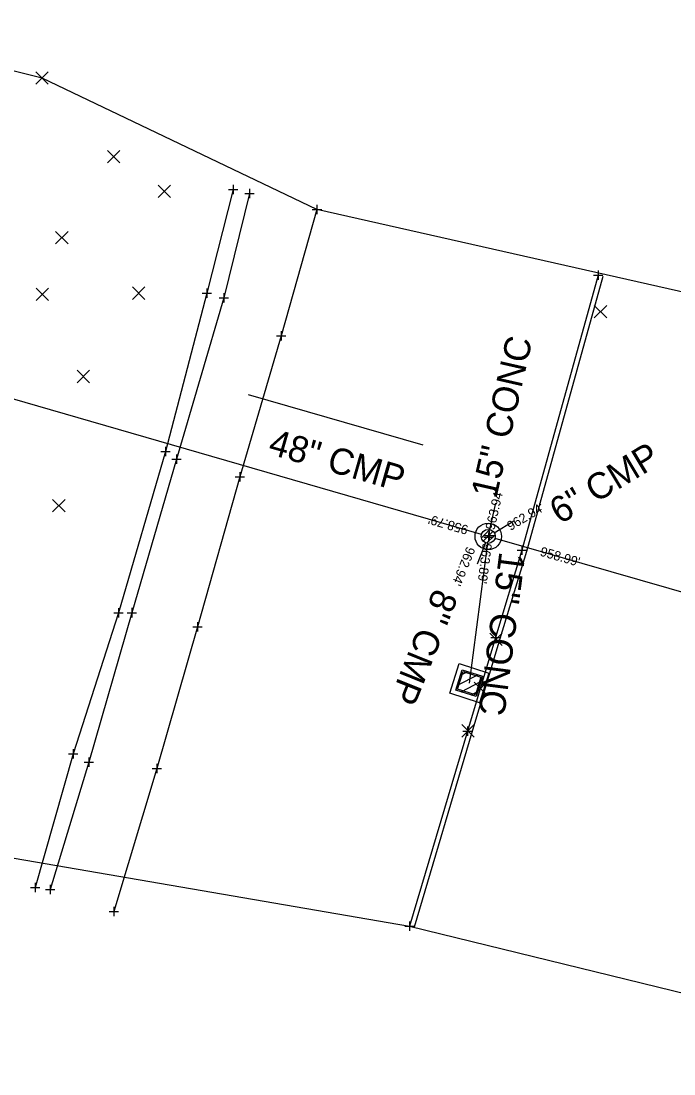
# Model space of a CAD drawing. Extents: x 160138 to 160780, y 488720 to 491073.
# Drawn here: x 160367.2 to 160437.1, y 489628.9 to 489741.6 of the extents above; entities that cross this region are included whole.
import ezdxf

# ---------------------------------------------------------------- set-up
doc = ezdxf.new("R2010")
doc.units = 0
for name, color, linetype in [('_CIVIL_CONSTRUCTION', 7, 'Continuous'), ('DR_X_Storm_Sewer', 7, 'Continuous'), ('DR_X_Text', 7, 'Continuous'), ('GE_X_Alignment_500_Bearings', 7, 'Continuous'), ('GE_X_Alignment_500_Stations', 7, 'Continuous'), ('PM_X_Channelizing_Line', 7, 'Continuous'), ('RD_X_Concrete_Barrier', 7, 'Continuous'), ('RW_X_CL', 7, 'Continuous'), ('RW_X_CL_100_Distances', 7, 'Continuous'), ('SC_Scratch1', 7, 'Continuous'), ('SV_X_Control_Cells_Found', 7, 'Continuous'), ('SV_X_Random_Point', 7, 'Continuous'), ('SV_X_Terrain_Boundary', 7, 'Continuous')]:
    doc.layers.add(name, color=color, linetype=linetype)

msp = doc.modelspace()

# ---------------------------------------------------------------- linework, layer by layer
at = {"layer": '_CIVIL_CONSTRUCTION'}
for p, q in [((160368.81, 489734.82), (160370.14, 489736.15)), ((160368.81, 489736.15), (160370.14, 489734.82)), ((160376.46, 489726.42), (160377.79, 489727.75)), ((160376.46, 489727.75), (160377.79, 489726.42)), ((160381.91, 489722.71), (160383.24, 489724.04)), ((160381.91, 489724.04), (160383.24, 489722.71)), ((160370.92, 489717.74), (160372.25, 489719.07)), ((160370.92, 489719.07), (160372.25, 489717.74)), ((160368.83, 489711.67), (160370.17, 489713.01)), ((160368.83, 489713.01), (160370.17, 489711.67)), ((160379.15, 489711.79), (160380.49, 489713.12)), ((160379.15, 489713.12), (160380.49, 489711.79)), ((160428.6, 489709.81), (160429.93, 489711.14)), ((160428.6, 489711.14), (160429.93, 489709.81)), ((160373.21, 489702.87), (160374.55, 489704.21)), ((160373.21, 489704.21), (160374.55, 489702.87)), ((160370.6, 489689.04), (160371.93, 489690.37)), ((160370.6, 489690.37), (160371.93, 489689.04)), ((160417.41, 489674.72), (160418.75, 489676.05)), ((160417.41, 489676.05), (160418.75, 489674.72)), ((160415.75, 489669.47), (160417.09, 489670.8)), ((160415.75, 489670.8), (160417.09, 489669.47)), ((160414.41, 489664.93), (160415.74, 489666.26)), ((160414.41, 489666.26), (160415.74, 489664.93))]:
    msp.add_line(p, q, dxfattribs=at)
at = {"layer": 'DR_X_Storm_Sewer'}
for p, q in [((160416.53, 489686.63), (160349.81, 489705.92)), ((160417.42, 489687.15), (160418.06, 489689.96)), ((160417.89, 489686.81), (160420, 489688.07)), ((160417.15, 489685.68), (160415.21, 489670.71)), ((160416.97, 489685.73), (160416.05, 489683.44)), ((160417.97, 489686.21), (160484.97, 489666.94))]:
    msp.add_line(p, q, dxfattribs=at)
at = {"layer": 'DR_X_Text'}
msp.add_line((160391.53, 489701.62), (160410.24, 489696.23), dxfattribs=at)
at = {"layer": 'GE_X_Alignment_500_Bearings'}
msp.add_lwpolyline([(160398.91, 489721.41), (160395.09, 489707.9), (160390.63, 489692.8), (160386.1, 489676.73), (160381.75, 489661.55), (160377.17, 489646.24)], dxfattribs=at)
at = {"layer": 'GE_X_Alignment_500_Stations'}
msp.add_lwpolyline([(160389.93, 489723.55), (160387.1, 489712.46), (160382.67, 489695.51), (160377.67, 489678.22), (160372.8, 489663.15), (160368.74, 489648.82)], dxfattribs=at)
at = {"layer": 'PM_X_Channelizing_Line'}
msp.add_lwpolyline([(160398.91, 489721.41), (160395.09, 489707.9), (160390.63, 489692.8), (160386.1, 489676.73), (160381.75, 489661.55), (160377.17, 489646.24)], dxfattribs=at)
at = {"layer": 'RD_X_Concrete_Barrier'}
for points in [[(160429.03, 489714.37), (160420.85, 489684.94), (160418.02, 489675.59), (160415.01, 489665.55), (160408.83, 489644.7)], [(160429.51, 489714.24), (160421.33, 489684.8), (160418.5, 489675.44), (160415.48, 489665.41), (160409.31, 489644.56)]]:
    msp.add_lwpolyline(points, dxfattribs=at)
at = {"layer": 'RW_X_CL'}
for p, q in [((160417.25, 489687.84), (160417.25, 489687.84)), ((160417.25, 489686.42), (160417.25, 489686.42)), ((160417.25, 489686.42), (160417.25, 489686.42)), ((160417.25, 489686.42), (160417.25, 489686.42)), ((160417.25, 489685.01), (160417.25, 489685.01)), ((160415.72, 489672.3), (160415.72, 489672.3)), ((160414.26, 489671.01), (160414.26, 489671.01)), ((160415.52, 489671.66), (160415.52, 489671.66)), ((160414.91, 489669.75), (160414.91, 489669.75)), ((160415.21, 489670.71), (160415.21, 489670.71)), ((160415.21, 489670.71), (160415.21, 489670.71)), ((160415.21, 489670.71), (160415.21, 489670.71)), ((160416.17, 489670.4), (160416.17, 489670.4)), ((160414.71, 489669.12), (160414.71, 489669.12))]:
    msp.add_line(p, q, dxfattribs=at)
msp.add_circle((160417.25, 489686.42), 0.75, dxfattribs=at)
at = {"layer": 'RW_X_CL_100_Distances'}
msp.add_lwpolyline([(160391.69, 489723.13), (160388.95, 489711.97), (160383.85, 489694.7), (160379.09, 489678.25), (160374.49, 489662.26), (160370.33, 489648.6)], dxfattribs=at)
at = {"layer": 'SV_X_Control_Cells_Found'}
for p, q in [((160416.52, 489686.27), (160417.4, 489687.16)), ((160416.71, 489685.9), (160417.77, 489686.96)), ((160417.07, 489685.69), (160417.98, 489686.6)), ((160414.28, 489671.55), (160415.07, 489671.95)), ((160413.94, 489670.47), (160416.14, 489671.61)), ((160414.35, 489669.78), (160416.47, 489670.88)), ((160415.43, 489669.44), (160416.13, 489669.8))]:
    msp.add_line(p, q, dxfattribs=at)
for points in [[(160414.13, 489672.8), (160417.31, 489671.79), (160416.3, 489668.61), (160413.12, 489669.62)], [(160414.47, 489672.14), (160416.65, 489671.45), (160415.96, 489669.27), (160413.78, 489669.96)], [(160414.56, 489671.96), (160416.47, 489671.36), (160415.87, 489669.45), (160413.96, 489670.05)]]:
    msp.add_lwpolyline(points, close=True, dxfattribs=at)
for radius in [1.42, 0.75, 0.75]:
    msp.add_circle((160417.25, 489686.42), radius, dxfattribs=at)
at = {"layer": 'SV_X_Random_Point'}
for p, q in [((160389.93, 489724.05), (160389.93, 489723.05)), ((160389.43, 489723.55), (160390.43, 489723.55)), ((160389.93, 489723.55), (160389.93, 489723.55)), ((160391.19, 489723.13), (160392.19, 489723.13)), ((160391.69, 489723.63), (160391.69, 489722.63)), ((160391.69, 489723.13), (160391.69, 489723.13)), ((160398.91, 489721.91), (160398.91, 489720.91)), ((160398.91, 489721.91), (160398.91, 489720.91)), ((160398.41, 489721.41), (160399.41, 489721.41)), ((160398.41, 489721.41), (160399.41, 489721.41)), ((160398.91, 489721.41), (160398.91, 489721.41)), ((160398.91, 489721.41), (160398.91, 489721.41)), ((160429.03, 489714.87), (160429.03, 489713.87)), ((160428.53, 489714.37), (160429.53, 489714.37)), ((160429.03, 489714.37), (160429.03, 489714.37)), ((160387.1, 489712.96), (160387.1, 489711.96)), ((160386.6, 489712.46), (160387.6, 489712.46)), ((160387.1, 489712.46), (160387.1, 489712.46)), ((160388.45, 489711.97), (160389.45, 489711.97)), ((160388.95, 489712.47), (160388.95, 489711.47)), ((160388.95, 489711.97), (160388.95, 489711.97)), ((160395.09, 489708.4), (160395.09, 489707.4)), ((160395.09, 489708.4), (160395.09, 489707.4)), ((160394.59, 489707.9), (160395.59, 489707.9)), ((160394.59, 489707.9), (160395.59, 489707.9)), ((160395.09, 489707.9), (160395.09, 489707.9)), ((160395.09, 489707.9), (160395.09, 489707.9)), ((160382.67, 489696.01), (160382.67, 489695.01)), ((160382.17, 489695.51), (160383.17, 489695.51)), ((160382.67, 489695.51), (160382.67, 489695.51)), ((160383.35, 489694.7), (160384.35, 489694.7)), ((160383.85, 489695.2), (160383.85, 489694.2)), ((160383.85, 489694.7), (160383.85, 489694.7)), ((160390.13, 489692.8), (160391.13, 489692.8)), ((160390.13, 489692.8), (160391.13, 489692.8)), ((160390.63, 489693.3), (160390.63, 489692.3)), ((160390.63, 489693.3), (160390.63, 489692.3)), ((160390.63, 489692.8), (160390.63, 489692.8)), ((160390.63, 489692.8), (160390.63, 489692.8)), ((160417.28, 489686.83), (160417.28, 489685.83)), ((160417.33, 489687), (160417.33, 489686)), ((160416.78, 489686.33), (160417.78, 489686.33)), ((160416.83, 489686.5), (160417.83, 489686.5)), ((160417.28, 489686.33), (160417.28, 489686.33)), ((160417.33, 489686.5), (160417.33, 489686.5)), ((160420.35, 489684.94), (160421.35, 489684.94)), ((160420.85, 489685.44), (160420.85, 489684.44)), ((160420.85, 489684.94), (160420.85, 489684.94)), ((160377.67, 489678.72), (160377.67, 489677.72)), ((160379.09, 489678.75), (160379.09, 489677.75)), ((160377.17, 489678.22), (160378.17, 489678.22)), ((160377.67, 489678.22), (160377.67, 489678.22)), ((160378.59, 489678.25), (160379.59, 489678.25)), ((160379.09, 489678.25), (160379.09, 489678.25)), ((160385.6, 489676.73), (160386.6, 489676.73)), ((160385.6, 489676.73), (160386.6, 489676.73)), ((160386.1, 489677.23), (160386.1, 489676.23)), ((160386.1, 489677.23), (160386.1, 489676.23)), ((160386.1, 489676.73), (160386.1, 489676.73)), ((160386.1, 489676.73), (160386.1, 489676.73)), ((160417.52, 489675.59), (160418.52, 489675.59)), ((160418.02, 489676.09), (160418.02, 489675.09)), ((160418.02, 489675.59), (160418.02, 489675.59)), ((160414.51, 489665.55), (160415.51, 489665.55)), ((160415.01, 489666.05), (160415.01, 489665.05)), ((160415.01, 489665.55), (160415.01, 489665.55)), ((160372.3, 489663.15), (160373.3, 489663.15)), ((160372.8, 489663.65), (160372.8, 489662.65)), ((160372.8, 489663.15), (160372.8, 489663.15)), ((160373.99, 489662.26), (160374.99, 489662.26)), ((160374.49, 489662.76), (160374.49, 489661.76)), ((160374.49, 489662.26), (160374.49, 489662.26)), ((160381.75, 489662.05), (160381.75, 489661.05)), ((160381.75, 489662.05), (160381.75, 489661.05)), ((160381.25, 489661.55), (160382.25, 489661.55)), ((160381.25, 489661.55), (160382.25, 489661.55)), ((160381.75, 489661.55), (160381.75, 489661.55)), ((160381.75, 489661.55), (160381.75, 489661.55)), ((160368.24, 489648.82), (160369.24, 489648.82)), ((160368.74, 489649.32), (160368.74, 489648.32)), ((160368.74, 489648.82), (160368.74, 489648.82)), ((160369.83, 489648.6), (160370.83, 489648.6)), ((160370.33, 489649.1), (160370.33, 489648.1)), ((160370.33, 489648.6), (160370.33, 489648.6)), ((160376.67, 489646.24), (160377.67, 489646.24)), ((160376.67, 489646.24), (160377.67, 489646.24)), ((160377.17, 489646.74), (160377.17, 489645.74)), ((160377.17, 489646.74), (160377.17, 489645.74)), ((160377.17, 489646.24), (160377.17, 489646.24)), ((160377.17, 489646.24), (160377.17, 489646.24)), ((160408.83, 489645.2), (160408.83, 489644.2)), ((160408.33, 489644.7), (160409.33, 489644.7)), ((160408.83, 489644.7), (160408.83, 489644.7))]:
    msp.add_line(p, q, dxfattribs=at)
at = {"layer": 'SV_X_Terrain_Boundary'}
msp.add_lwpolyline([(160560.41, 489729.32), (160491.05, 489700.61), (160398.91, 489721.41), (160369.48, 489735.48), (160345.1, 489741.59), (160340, 489741.44), (160332.02, 489740.13), (160312.1, 489734.79), (160313.36, 489709.7), (160316.29, 489695.42), (160319.47, 489684.93), (160347.56, 489655.2), (160408.83, 489644.7), (160473.47, 489628.86), (160504.76, 489630.54), (160514.91, 489637.89), (160547.86, 489638.24)], dxfattribs=at)

# ---------------------------------------------------------------- texts
at = {"layer": 'DR_X_Text'}
for s, rotation, p in [('15" CONC', 77.1684, (160418.1, 489690.36)), ('48" CMP', 343.9128, (160393.56, 489695.28)), ('6" CMP', 31.004, (160424.92, 489687.66)), ('15" CONC', 262.6157, (160418.45, 489684.85)), ('8" CMP', 248.1094, (160411.47, 489680.97))]:
    msp.add_text(s, height=2.8, rotation=rotation, dxfattribs=at).set_placement(p)
at = {"layer": 'SC_Scratch1'}
for s, rotation, p in [("963.94'", 77.1684, (160417.9, 489687.04)), ("962.94'", 31.004, (160419.63, 489686.99)), ("958.79'", 163.8709, (160415.19, 489687.54)), ("963.89'", 262.6157, (160416.66, 489685.74)), ("962.94'", 248.1094, (160414.96, 489685.41)), ("958.99'", 343.9545, (160422.72, 489684.37))]:
    msp.add_text(s, height=1, rotation=rotation, dxfattribs=at).set_placement(p)

doc.saveas('drawing.dxf')
